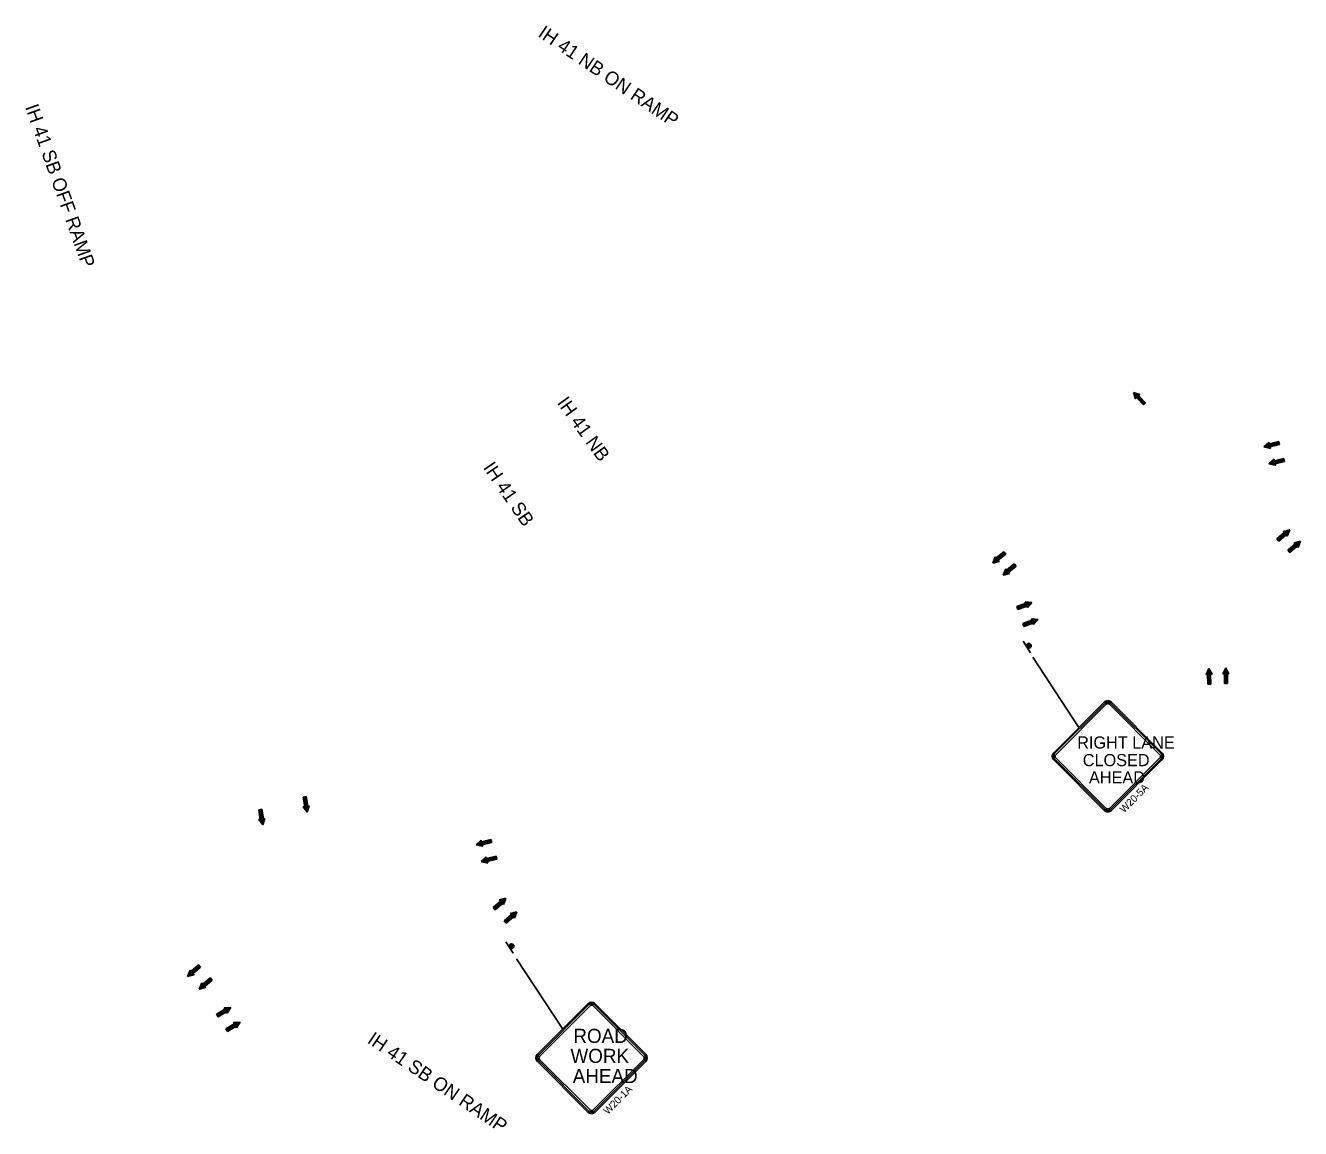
# Model space of a CAD drawing. Extents: x 358662 to 361839, y 132407 to 133741.
# Drawn here: x 358662 to 359598, y 132425 to 133235 of the extents above; entities that cross this region are included whole.
import ezdxf

# ---------------------------------------------------------------- set-up
doc = ezdxf.new("R2010")
doc.units = 0
for name, color, linetype in [('E_BLD_Dash', 7, 'Continuous'), ('E_BLD_Footing', 7, 'Continuous'), ('E_MISCPROP_ShtDash', 7, 'Continuous'), ('P_FTMS_LaneLbl', 7, 'Continuous')]:
    doc.layers.add(name, color=color, linetype=linetype)

msp = doc.modelspace()

# ---------------------------------------------------------------- linework, layer by layer
at = {"layer": 'E_BLD_Dash'}
for p, q in [((359400.02, 132774.47), (359394.7, 132782.93)), ((359019.85, 132553.76), (359014.53, 132562.23))]:
    msp.add_line(p, q, dxfattribs=at)
for centre, radius in [((359398.86, 132779.61), 1.75), ((359398.86, 132779.61), 1), ((359398.86, 132779.61), 0.25), ((359018.69, 132558.9), 1.75), ((359018.69, 132558.9), 1), ((359018.69, 132558.9), 0.25)]:
    msp.add_circle(centre, radius, dxfattribs=at)
at = {"layer": 'E_BLD_Footing'}
for p, q in [((359475.76, 132965.59), (359477.25, 132960.89)), ((359475.76, 132965.59), (359480.47, 132964.04)), ((359483.67, 132957.21), (359475.89, 132965.18)), ((359483.35, 132956.89), (359476.19, 132964.23)), ((359483.99, 132957.52), (359476.3, 132965.41)), ((359478.03, 132961.7), (359476.49, 132963.28)), ((359484.31, 132957.84), (359477.22, 132965.1)), ((359477.25, 132960.89), (359480.47, 132964.04)), ((359479.65, 132963.27), (359478.15, 132964.8)), ((359479.97, 132963.58), (359479.08, 132964.49)), ((359484.64, 132958.15), (359479.66, 132963.25)), ((359480.29, 132963.9), (359480, 132964.19)), ((359477.71, 132961.38), (359476.79, 132962.32)), ((359477.39, 132961.07), (359477.09, 132961.37)), ((359483.03, 132956.58), (359478.05, 132961.68)), ((359483.03, 132956.58), (359484.64, 132958.15)), ((359483.83, 132957.36), (359483.83, 132957.36)), ((359571.54, 132925.68), (359575.26, 132928.95)), ((359571.54, 132925.68), (359576.34, 132924.59)), ((359582.77, 132928.26), (359571.95, 132925.59)), ((359582.66, 132928.7), (359571.96, 132926.05)), ((359582.55, 132929.14), (359572.69, 132926.7)), ((359582.88, 132927.82), (359572.93, 132925.37)), ((359575.5, 132927.86), (359573.43, 132927.34)), ((359576.04, 132925.67), (359573.9, 132925.14)), ((359575.4, 132928.29), (359574.16, 132927.99)), ((359575.29, 132928.73), (359574.89, 132928.63)), ((359576.34, 132924.59), (359575.26, 132928.95)), ((359582.44, 132929.57), (359575.53, 132927.86)), ((359582.98, 132927.39), (359576.07, 132925.68)), ((359582.98, 132927.39), (359582.44, 132929.57)), ((359582.71, 132928.48), (359582.71, 132928.48)), ((359576.15, 132925.24), (359574.88, 132924.92)), ((359575.26, 132913.27), (359578.98, 132916.54)), ((359586.38, 132916.29), (359575.68, 132913.64)), ((359576.26, 132924.8), (359575.85, 132924.7)), ((359586.27, 132916.73), (359576.42, 132914.29)), ((359579.01, 132916.32), (359578.61, 132916.22)), ((359580.06, 132912.18), (359578.98, 132916.54)), ((359586.17, 132917.16), (359579.25, 132915.45)), ((359586.71, 132914.98), (359586.17, 132917.16)), ((359575.26, 132913.27), (359580.06, 132912.18)), ((359586.49, 132915.85), (359575.68, 132913.18)), ((359586.6, 132915.41), (359576.65, 132912.96)), ((359579.23, 132915.45), (359577.15, 132914.93)), ((359579.77, 132913.26), (359577.63, 132912.73)), ((359579.12, 132915.88), (359577.88, 132915.58)), ((359579.88, 132912.83), (359578.6, 132912.51)), ((359579.98, 132912.39), (359579.57, 132912.29)), ((359586.71, 132914.98), (359579.79, 132913.27)), ((359586.44, 132916.07), (359586.44, 132916.07)), ((359581.12, 132858.04), (359586.48, 132862.73)), ((359581.41, 132857.7), (359589.13, 132864.45)), ((359581.71, 132857.36), (359590.1, 132864.7)), ((359582.01, 132857.03), (359590.3, 132864.28)), ((359582.3, 132856.69), (359589.95, 132863.37)), ((359582.6, 132856.35), (359587.96, 132861.04)), ((359590.51, 132864.8), (359585.74, 132863.58)), ((359585.74, 132863.58), (359588.7, 132860.19)), ((359585.91, 132863.42), (359586.23, 132863.7)), ((359586.2, 132863.09), (359587.19, 132863.95)), ((359586.5, 132862.75), (359588.16, 132864.2)), ((359587.98, 132861.05), (359589.59, 132862.46)), ((359588.28, 132860.71), (359589.24, 132861.55)), ((359588.57, 132860.38), (359588.88, 132860.65)), ((359590.51, 132864.8), (359588.7, 132860.19)), ((359581.12, 132858.04), (359582.6, 132856.35)), ((359581.86, 132857.2), (359581.86, 132857.2)), ((359589.04, 132849.69), (359594.4, 132854.38)), ((359589.33, 132849.35), (359597.05, 132856.1)), ((359589.63, 132849.01), (359598.02, 132856.34)), ((359589.93, 132848.67), (359598.22, 132855.93)), ((359590.22, 132848.34), (359597.87, 132855.02)), ((359590.52, 132848), (359595.88, 132852.68)), ((359598.43, 132856.45), (359593.66, 132855.23)), ((359593.66, 132855.23), (359596.62, 132851.84)), ((359593.83, 132855.07), (359594.14, 132855.35)), ((359594.12, 132854.73), (359595.11, 132855.6)), ((359594.42, 132854.4), (359596.08, 132855.85)), ((359595.9, 132852.7), (359597.51, 132854.11)), ((359596.2, 132852.36), (359597.16, 132853.2)), ((359596.49, 132852.02), (359596.8, 132852.29)), ((359598.43, 132856.45), (359596.62, 132851.84)), ((359372.27, 132840.36), (359374.16, 132844.94)), ((359372.27, 132840.36), (359377.06, 132841.5)), ((359380.91, 132847.98), (359372.48, 132840.88)), ((359381.2, 132847.63), (359372.68, 132840.46)), ((359380.62, 132848.32), (359372.86, 132841.79)), ((359374.87, 132844.07), (359373.23, 132842.69)), ((359374.58, 132844.41), (359373.6, 132843.59)), ((359381.49, 132847.29), (359373.65, 132840.69)), ((359374.29, 132844.75), (359373.97, 132844.49)), ((359377.06, 132841.5), (359374.16, 132844.94)), ((359376.31, 132842.34), (359374.63, 132840.92)), ((359380.33, 132848.67), (359374.89, 132844.08)), ((359376.6, 132842), (359375.6, 132841.15)), ((359381.78, 132846.95), (359376.34, 132842.36)), ((359376.89, 132841.65), (359376.57, 132841.38)), ((359381.78, 132846.95), (359380.33, 132848.67)), ((359381.06, 132847.81), (359381.06, 132847.81)), ((359589.04, 132849.69), (359590.52, 132848)), ((359589.78, 132848.84), (359589.78, 132848.84)), ((359379.89, 132831.47), (359381.78, 132836.05)), ((359379.89, 132831.47), (359384.68, 132832.6)), ((359388.54, 132839.08), (359380.1, 132831.99)), ((359388.83, 132838.74), (359380.3, 132831.57)), ((359388.25, 132839.43), (359380.48, 132832.89)), ((359382.49, 132835.17), (359380.85, 132833.79)), ((359382.2, 132835.51), (359381.22, 132834.69)), ((359389.12, 132838.4), (359381.27, 132831.8)), ((359381.91, 132835.86), (359381.59, 132835.59)), ((359384.68, 132832.6), (359381.78, 132836.05)), ((359383.94, 132833.45), (359382.25, 132832.03)), ((359387.96, 132839.77), (359382.51, 132835.19)), ((359384.23, 132833.1), (359383.22, 132832.26)), ((359389.4, 132838.05), (359383.96, 132833.47)), ((359384.51, 132832.76), (359384.19, 132832.49)), ((359389.4, 132838.05), (359387.96, 132839.77)), ((359388.68, 132838.91), (359388.68, 132838.91)), ((359389.92, 132808.32), (359396.59, 132810.82)), ((359389.92, 132808.32), (359390.71, 132806.21)), ((359390.08, 132807.9), (359399.68, 132811.49)), ((359390.24, 132807.48), (359400.67, 132811.38)), ((359390.32, 132807.27), (359390.32, 132807.27)), ((359390.4, 132807.06), (359400.72, 132810.92)), ((359390.55, 132806.63), (359400.06, 132810.19)), ((359390.71, 132806.21), (359397.38, 132808.71)), ((359401.09, 132811.34), (359396.2, 132811.87)), ((359396.2, 132811.87), (359397.78, 132807.66)), ((359396.3, 132811.67), (359396.7, 132811.82)), ((359396.46, 132811.25), (359397.69, 132811.71)), ((359396.62, 132810.83), (359398.68, 132811.6)), ((359397.41, 132808.72), (359399.41, 132809.47)), ((359397.56, 132808.3), (359398.76, 132808.75)), ((359397.72, 132807.88), (359398.11, 132808.02)), ((359401.09, 132811.34), (359397.78, 132807.66)), ((359394.42, 132795.92), (359401.09, 132798.42)), ((359394.42, 132795.92), (359395.21, 132793.81)), ((359394.58, 132795.5), (359404.17, 132799.09)), ((359394.74, 132795.08), (359405.17, 132798.98)), ((359394.81, 132794.86), (359394.81, 132794.86)), ((359394.89, 132794.65), (359405.21, 132798.52)), ((359395.05, 132794.23), (359404.56, 132797.79)), ((359395.21, 132793.81), (359401.88, 132796.31)), ((359405.59, 132798.94), (359400.7, 132799.47)), ((359400.7, 132799.47), (359402.28, 132795.26)), ((359400.8, 132799.27), (359401.19, 132799.42)), ((359400.96, 132798.85), (359402.19, 132799.31)), ((359401.11, 132798.43), (359403.18, 132799.2)), ((359401.9, 132796.32), (359403.91, 132797.07)), ((359402.06, 132795.9), (359403.26, 132796.34)), ((359402.22, 132795.48), (359402.6, 132795.62)), ((359405.59, 132798.94), (359402.28, 132795.26)), ((359531.12, 132762.97), (359529.01, 132758.52)), ((359529.01, 132758.52), (359533.51, 132758.63)), ((359529.23, 132758.55), (359529.22, 132758.97)), ((359529.68, 132758.56), (359529.65, 132759.87)), ((359530.13, 132758.57), (359530.08, 132760.78)), ((359530.31, 132751.42), (359530.14, 132758.54)), ((359530.76, 132751.44), (359530.51, 132761.68)), ((359531.21, 132751.45), (359530.94, 132762.58)), ((359531.12, 132762.97), (359533.51, 132758.63)), ((359531.66, 132751.46), (359531.39, 132762.47)), ((359532.11, 132751.47), (359531.86, 132761.62)), ((359532.38, 132758.62), (359532.33, 132760.77)), ((359532.56, 132751.48), (359532.38, 132758.6)), ((359532.83, 132758.64), (359532.8, 132759.91)), ((359533.28, 132758.65), (359533.27, 132759.06)), ((359543.45, 132763.37), (359541.34, 132758.92)), ((359541.34, 132758.92), (359545.84, 132759.03)), ((359541.57, 132758.95), (359541.56, 132759.38)), ((359542.02, 132758.96), (359541.99, 132760.28)), ((359542.47, 132758.97), (359542.41, 132761.18)), ((359542.64, 132751.83), (359542.47, 132758.95)), ((359543.09, 132751.84), (359542.84, 132762.08)), ((359543.54, 132751.85), (359543.27, 132762.99)), ((359543.45, 132763.37), (359545.84, 132759.03)), ((359543.99, 132751.86), (359543.72, 132762.88)), ((359544.44, 132751.87), (359544.19, 132762.02)), ((359544.72, 132759.03), (359544.66, 132761.17)), ((359544.89, 132751.88), (359544.72, 132759)), ((359545.17, 132759.04), (359545.14, 132760.31)), ((359545.62, 132759.05), (359545.61, 132759.46)), ((359530.31, 132751.42), (359532.56, 132751.48)), ((359531.43, 132751.45), (359531.43, 132751.45)), ((359542.64, 132751.83), (359544.89, 132751.88)), ((359543.76, 132751.86), (359543.76, 132751.86)), ((358867.8, 132668.79), (358865.58, 132668.43)), ((358865.58, 132668.43), (358866.74, 132661.4)), ((358866.03, 132668.5), (358867.68, 132658.48)), ((358866.47, 132668.57), (358868.27, 132657.7)), ((358866.69, 132668.61), (358866.69, 132668.61)), ((358866.92, 132668.65), (358868.73, 132657.65)), ((358867.36, 132668.72), (358869.03, 132658.61)), ((358867.8, 132668.79), (358868.96, 132661.77)), ((358835.15, 132659.5), (358832.93, 132659.13)), ((358832.93, 132659.13), (358834.09, 132652.1)), ((358833.37, 132659.21), (358835.02, 132649.19)), ((358833.81, 132659.28), (358835.61, 132648.41)), ((358834.04, 132659.31), (358834.04, 132659.31)), ((358834.26, 132659.35), (358836.07, 132648.36)), ((358834.7, 132659.42), (358836.37, 132649.31)), ((358835.15, 132659.5), (358836.31, 132652.47)), ((358870.07, 132661.95), (358865.63, 132661.21)), ((358868.6, 132657.25), (358865.63, 132661.21)), ((358865.86, 132661.23), (358865.93, 132660.82)), ((358866.3, 132661.3), (358866.51, 132660.04)), ((358866.75, 132661.37), (358867.1, 132659.26)), ((358868.6, 132657.25), (358870.07, 132661.95)), ((358868.97, 132661.74), (358869.33, 132659.56)), ((358869.41, 132661.81), (358869.63, 132660.52)), ((358869.86, 132661.89), (358869.92, 132661.47)), ((358837.42, 132652.65), (358832.98, 132651.92)), ((358835.94, 132647.96), (358832.98, 132651.92)), ((358833.2, 132651.93), (358833.27, 132651.53)), ((358833.65, 132652.01), (358833.85, 132650.75)), ((358834.09, 132652.08), (358834.44, 132649.97)), ((358835.94, 132647.96), (358837.42, 132652.65)), ((358836.31, 132652.44), (358836.67, 132650.27)), ((358836.75, 132652.52), (358836.97, 132651.22)), ((358837.2, 132652.59), (358837.27, 132652.17)), ((358992.64, 132633.46), (358996.36, 132636.73)), ((359003.76, 132636.48), (358993.06, 132633.83)), ((359003.87, 132636.04), (358993.06, 132633.37)), ((359003.65, 132636.91), (358993.8, 132634.48)), ((359003.98, 132635.6), (358994.03, 132633.14)), ((358996.61, 132635.64), (358994.53, 132635.12)), ((358996.5, 132636.07), (358995.26, 132635.77)), ((358996.39, 132636.51), (358995.99, 132636.41)), ((358997.44, 132632.36), (358996.36, 132636.73)), ((359003.55, 132637.35), (358996.63, 132635.64)), ((359004.09, 132635.17), (358997.17, 132633.46)), ((359004.09, 132635.17), (359003.55, 132637.35)), ((359003.82, 132636.26), (359003.82, 132636.26)), ((358992.64, 132633.46), (358997.44, 132632.36)), ((358997.15, 132633.45), (358995, 132632.92)), ((358997.25, 132633.01), (358995.98, 132632.7)), ((358997.36, 132632.58), (358996.95, 132632.48)), ((358996.37, 132621.05), (359000.08, 132624.32)), ((358996.37, 132621.05), (359001.16, 132619.95)), ((359007.59, 132623.63), (358996.78, 132620.96)), ((359007.49, 132624.07), (358996.79, 132621.42)), ((359007.38, 132624.5), (358997.52, 132622.07)), ((359007.7, 132623.19), (358997.75, 132620.73)), ((359000.33, 132623.23), (358998.25, 132622.71)), ((359000.87, 132621.04), (358998.73, 132620.51)), ((359000.22, 132623.66), (358998.98, 132623.36)), ((359000.98, 132620.6), (358999.7, 132620.29)), ((359000.11, 132624.1), (358999.72, 132624)), ((359001.16, 132619.95), (359000.08, 132624.32)), ((359007.27, 132624.94), (359000.36, 132623.23)), ((359001.09, 132620.17), (359000.68, 132620.07)), ((359007.81, 132622.76), (359000.9, 132621.05)), ((359007.81, 132622.76), (359007.27, 132624.94)), ((359007.54, 132623.85), (359007.54, 132623.85)), ((359005.1, 132587.35), (359010.47, 132592.02)), ((359005.39, 132587.01), (359013.13, 132593.74)), ((359005.69, 132586.67), (359014.09, 132593.98)), ((359005.99, 132586.33), (359014.3, 132593.57)), ((359006.28, 132585.99), (359013.94, 132592.66)), ((359006.58, 132585.65), (359011.95, 132590.33)), ((359014.5, 132594.09), (359009.74, 132592.88)), ((359009.74, 132592.88), (359012.69, 132589.48)), ((359009.9, 132592.72), (359010.22, 132593)), ((359010.2, 132592.38), (359011.19, 132593.24)), ((359010.49, 132592.04), (359012.16, 132593.49)), ((359011.97, 132590.34), (359013.58, 132591.75)), ((359012.26, 132590), (359013.23, 132590.84)), ((359012.56, 132589.67), (359012.87, 132589.94)), ((359014.5, 132594.09), (359012.69, 132589.48)), ((359005.1, 132587.35), (359006.58, 132585.65)), ((359005.84, 132586.5), (359005.84, 132586.5)), ((359013.2, 132577.46), (359018.57, 132582.14)), ((359013.5, 132577.12), (359021.23, 132583.85)), ((359013.79, 132576.78), (359022.2, 132584.1)), ((359014.09, 132576.44), (359022.4, 132583.68)), ((359014.38, 132576.1), (359022.04, 132582.77)), ((359014.68, 132575.76), (359020.05, 132580.44)), ((359022.61, 132584.2), (359017.84, 132582.99)), ((359017.84, 132582.99), (359020.79, 132579.59)), ((359018, 132582.83), (359018.32, 132583.11)), ((359018.3, 132582.49), (359019.29, 132583.36)), ((359018.59, 132582.15), (359020.26, 132583.6)), ((359020.07, 132580.46), (359021.69, 132581.86)), ((359020.37, 132580.12), (359021.33, 132580.95)), ((359020.66, 132579.78), (359020.97, 132580.05)), ((359022.61, 132584.2), (359020.79, 132579.59)), ((359013.2, 132577.46), (359014.68, 132575.76)), ((359013.94, 132576.61), (359013.94, 132576.61)), ((358789.24, 132544.43), (358780.87, 132537.27)), ((358789.53, 132544.09), (358781.07, 132536.85)), ((358788.95, 132544.77), (358781.23, 132538.17)), ((358789.83, 132543.75), (358782.04, 132537.09)), ((358788.65, 132545.12), (358783.24, 132540.49)), ((358790.12, 132543.41), (358784.71, 132538.78)), ((358790.12, 132543.41), (358788.65, 132545.12)), ((358789.39, 132544.26), (358789.39, 132544.26)), ((358780.66, 132536.75), (358782.51, 132541.34)), ((358780.66, 132536.75), (358785.44, 132537.92)), ((358783.22, 132540.47), (358781.6, 132539.08)), ((358782.93, 132540.81), (358781.96, 132539.98)), ((358782.64, 132541.15), (358782.33, 132540.89)), ((358785.44, 132537.92), (358782.51, 132541.34)), ((358784.69, 132538.76), (358783.01, 132537.32)), ((358784.98, 132538.42), (358783.98, 132537.56)), ((358785.27, 132538.08), (358784.95, 132537.8)), ((358797.81, 132535.04), (358789.43, 132527.87)), ((358798.1, 132534.7), (358789.64, 132527.45)), ((358797.51, 132535.38), (358789.8, 132528.78)), ((358798.39, 132534.36), (358790.61, 132527.69)), ((358797.22, 132535.72), (358791.81, 132531.09)), ((358798.68, 132534.01), (358793.27, 132529.38)), ((358798.68, 132534.01), (358797.22, 132535.72)), ((358797.95, 132534.87), (358797.95, 132534.87)), ((358789.22, 132527.35), (358791.08, 132531.94)), ((358789.22, 132527.35), (358794, 132528.53)), ((358791.79, 132531.07), (358790.16, 132529.68)), ((358791.5, 132531.42), (358790.53, 132530.59)), ((358791.21, 132531.76), (358790.89, 132531.49)), ((358794, 132528.53), (358791.08, 132531.94)), ((358793.25, 132529.37), (358791.58, 132527.93)), ((358793.55, 132529.02), (358792.55, 132528.17)), ((358793.84, 132528.68), (358793.52, 132528.41)), ((358802.1, 132508.56), (358810.92, 132513.8)), ((358802.34, 132508.18), (358811.91, 132513.87)), ((358802.56, 132507.79), (358812.04, 132513.42)), ((358812.33, 132513.9), (358807.43, 132513.56)), ((358807.43, 132513.56), (358809.72, 132509.69)), ((358807.56, 132513.38), (358807.92, 132513.59)), ((358807.79, 132512.99), (358808.92, 132513.66)), ((358808.02, 132512.6), (358809.92, 132513.73)), ((358812.33, 132513.9), (358809.72, 132509.69)), ((358801.88, 132508.95), (358808, 132512.59)), ((358801.88, 132508.95), (358803.02, 132507.02)), ((358802.45, 132507.98), (358802.45, 132507.98)), ((358802.79, 132507.4), (358811.52, 132512.59)), ((358803.02, 132507.02), (358809.15, 132510.65)), ((358809.17, 132510.67), (358811.01, 132511.76)), ((358809.4, 132510.28), (358810.5, 132510.93)), ((358809.63, 132509.89), (358809.98, 132510.1)), ((358808.71, 132498.23), (358814.83, 132501.87)), ((358808.71, 132498.23), (358809.86, 132496.3)), ((358808.94, 132497.84), (358817.75, 132503.08)), ((358809.17, 132497.46), (358818.75, 132503.15)), ((358809.28, 132497.26), (358809.28, 132497.26)), ((358809.4, 132497.07), (358818.87, 132502.7)), ((358809.63, 132496.68), (358818.36, 132501.87)), ((358809.86, 132496.3), (358815.98, 132499.93)), ((358819.17, 132503.17), (358814.26, 132502.84)), ((358814.26, 132502.84), (358816.56, 132498.97)), ((358814.4, 132502.65), (358814.76, 132502.87)), ((358814.63, 132502.27), (358815.76, 132502.94)), ((358814.86, 132501.88), (358816.75, 132503.01)), ((358816, 132499.95), (358817.85, 132501.04)), ((358816.23, 132499.56), (358817.33, 132500.21)), ((358816.46, 132499.17), (358816.82, 132499.38)), ((358819.17, 132503.17), (358816.56, 132498.97))]:
    msp.add_line(p, q, dxfattribs=at)
at = {"layer": 'E_MISCPROP_ShtDash'}
for points in [[(359454.19, 132738.17), (359417.07, 132701.05)], [(359496.62, 132701.05), (359459.5, 132738.17)], [(359454.87, 132737.5), (359417.75, 132700.38)], [(359455.71, 132736.66), (359418.59, 132699.54)], [(359495.11, 132699.54), (359457.98, 132736.66)], [(359495.95, 132700.38), (359458.82, 132737.5)], [(359417.07, 132695.75), (359454.19, 132658.62)], [(359417.75, 132696.42), (359454.87, 132659.3)], [(359418.59, 132697.26), (359455.71, 132660.14)], [(359458.01, 132660.17), (359495.12, 132697.28)], [(359458.85, 132659.33), (359495.96, 132696.44)], [(359459.53, 132658.65), (359496.64, 132695.76)], [(359074.85, 132516.65), (359037.73, 132479.53)], [(359075.53, 132515.98), (359038.4, 132478.86)], [(359076.37, 132515.14), (359039.25, 132478.01)], [(359115.77, 132478.01), (359078.64, 132515.14)], [(359116.61, 132478.86), (359079.48, 132515.98)], [(359117.28, 132479.53), (359080.16, 132516.65)], [(359037.73, 132474.23), (359074.85, 132437.1)], [(359038.4, 132474.9), (359075.53, 132437.78)], [(359039.25, 132475.74), (359076.37, 132438.62)], [(359078.67, 132438.65), (359115.78, 132475.76)], [(359079.51, 132437.81), (359116.62, 132474.92)], [(359080.19, 132437.13), (359117.3, 132474.24)]]:
    msp.add_lwpolyline(points, dxfattribs=at)
for centre, radius, start, end in [((359456.85, 132735.52), 3.75, 44.99811, 135), ((359456.85, 132735.52), 2.8, 44.99811, 135), ((359456.85, 132735.52), 1.61, 44.99811, 135), ((359419.72, 132698.4), 3.75, 135, 225), ((359493.97, 132698.4), 3.75, 315, 45), ((359419.72, 132698.4), 2.8, 135, 225), ((359419.72, 132698.4), 1.61, 135, 225), ((359493.97, 132698.4), 1.61, 315, 45), ((359493.97, 132698.4), 2.8, 315, 45), ((359456.85, 132661.28), 3.75, 225.00722, 315.65087), ((359456.85, 132661.28), 2.8, 225.00722, 315.65087), ((359456.85, 132661.28), 1.61, 225.00722, 315.65087), ((359077.51, 132514), 3.75, 44.99811, 135), ((359077.51, 132514), 2.8, 44.99811, 135), ((359077.51, 132514), 1.61, 44.99811, 135), ((359040.38, 132476.88), 3.75, 135, 225), ((359040.38, 132476.88), 2.8, 135, 225), ((359040.38, 132476.88), 1.61, 135, 225), ((359114.63, 132476.88), 1.61, 315, 45), ((359114.63, 132476.88), 2.8, 315, 45), ((359114.63, 132476.88), 3.75, 315, 45), ((359077.51, 132439.75), 1.61, 225.00722, 315.65087), ((359077.51, 132439.75), 3.75, 225.00722, 315.65087), ((359077.51, 132439.75), 2.8, 225.00722, 315.65087)]:
    msp.add_arc(centre, radius, start, end, dxfattribs=at)
at = {"layer": 'P_FTMS_LaneLbl'}
for p, q in [((359401.63, 132771.22), (359435.63, 132719.61)), ((359022.29, 132549.7), (359056.29, 132498.09))]:
    msp.add_line(p, q, dxfattribs=at)

# ---------------------------------------------------------------- texts
at = {"layer": 'E_MISCPROP_ShtDash'}
for s, height, p in [('RIGHT LANE', 8.929, (359434.34, 132704.09)), ('CLOSED', 8.929, (359438.44, 132691.15)), ('AHEAD', 8.929, (359442.99, 132678.46)), ('ROAD', 10.357, (359064.12, 132487.88)), ('WORK', 10.357, (359061.97, 132473.18)), ('AHEAD', 10.357, (359063.65, 132458.4))]:
    msp.add_text(s, height=height, dxfattribs=at).set_placement(p)
for s, p in [('W20-5A', (359468.76, 132656.46)), ('W20-1A', (359089.42, 132434.94))]:
    msp.add_text(s, height=5.4, rotation=45, dxfattribs=at).set_placement(p)
at = {"layer": 'P_FTMS_LaneLbl'}
for s, rotation, p in [('IH 41 NB ON RAMP', 325.92706, (359037.46, 133227.59)), ('IH 41 SB OFF RAMP', 289.64094, (358661.12, 133175.34)), ('IH 41 NB', 305.82096, (359051.73, 132958)), ('IH 41 SB', 304.46134, (358997.4, 132910.4)), ('IH 41 SB ON RAMP', 325.92706, (358912.03, 132488.36))]:
    msp.add_text(s, height=10, rotation=rotation, dxfattribs=at).set_placement(p)

doc.saveas('drawing.dxf')
